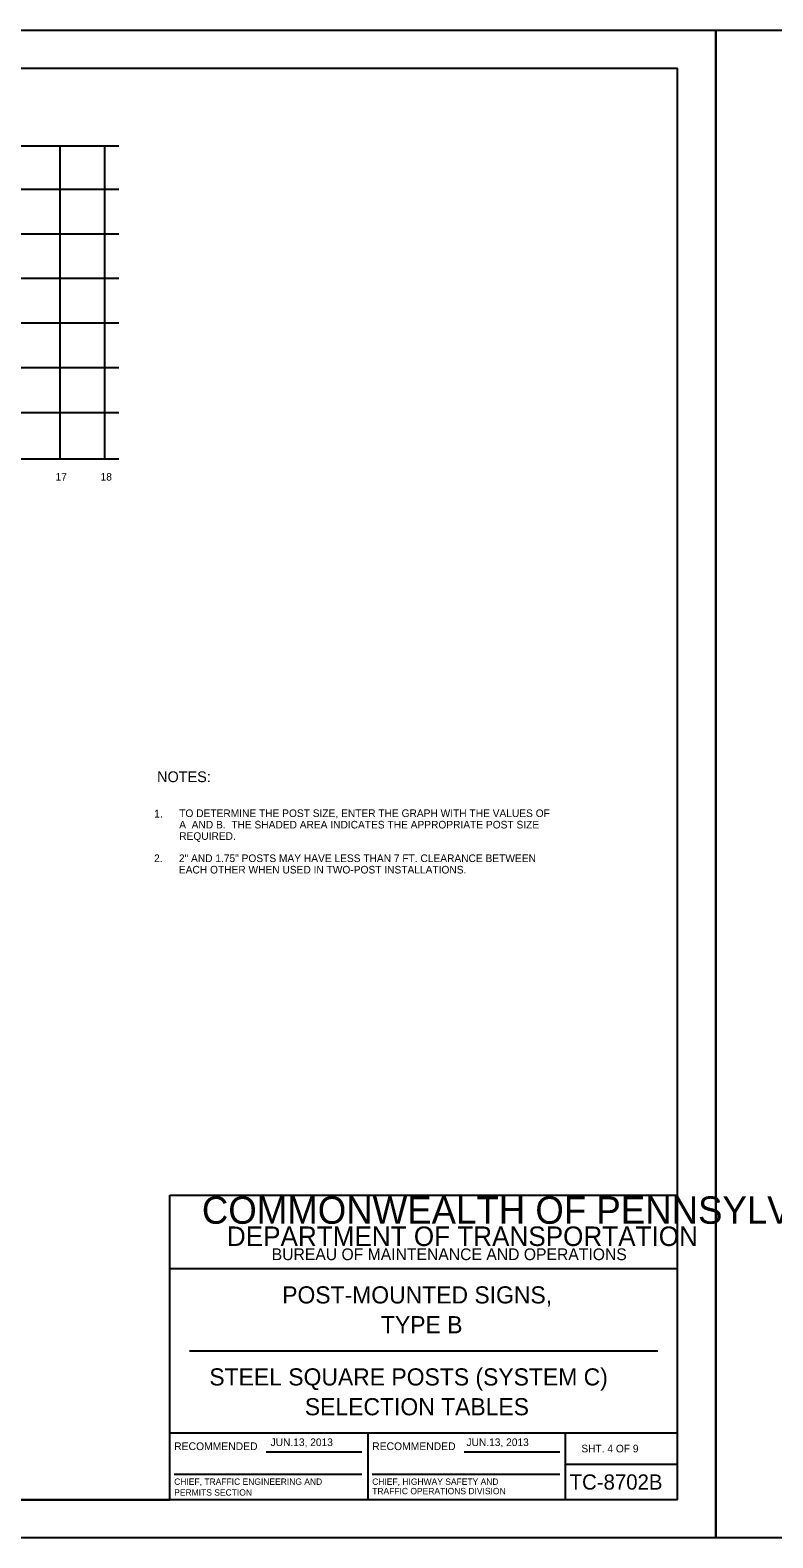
# Model space of a CAD drawing. Extents: x 644358 to 648627, y 294594 to 295782.
# Drawn here: x 647452 to 647745, y 295188 to 295782 of the extents above; entities that cross this region are included whole.
import ezdxf

# ---------------------------------------------------------------- set-up
doc = ezdxf.new("R2010")
doc.units = 0
for name, color, linetype in [('1', 7, 'Continuous'), ('2', 7, 'Continuous'), ('4', 7, 'Continuous'), ('PLT-BNDY', 7, 'Continuous')]:
    doc.layers.add(name, color=color, linetype=linetype)

msp = doc.modelspace()

# ---------------------------------------------------------------- linework, layer by layer
at = {"layer": '1'}
for p, q in [((646921.31, 295766.63), (647707.31, 295766.63)), ((647707.31, 295202.63), (647707.31, 295766.63)), ((647507.31, 295202.63), (647507.31, 295322.63)), ((647507.31, 295322.63), (647707.31, 295322.63)), ((647707.31, 295293.63), (647507.31, 295293.63)), ((647515.06, 295261.31), (647699.56, 295261.31)), ((647507.31, 295229), (647707.31, 295229)), ((647585.31, 295229), (647585.31, 295202.63)), ((647663.19, 295202.63), (647663.19, 295229)), ((647545.24, 295221.57), (647582.87, 295221.57)), ((647623.24, 295221.57), (647660.87, 295221.57)), ((647508.99, 295212.68), (647582.87, 295212.68)), ((647586.99, 295212.68), (647660.87, 295212.68)), ((647663.19, 295216.63), (647707.31, 295216.63)), ((647707.31, 295202.63), (646921.31, 295202.63)), ((646921.31, 295202.63), (647507.31, 295202.63))]:
    msp.add_line(p, q, dxfattribs=at)
at = {"layer": '2'}
for p, q in [((647487.16, 295735.97), (647252.91, 295735.97)), ((647464.03, 295612.54), (647464.03, 295735.97)), ((647481.66, 295612.54), (647481.66, 295735.97)), ((647487.16, 295718.91), (647252.91, 295718.91)), ((647487.16, 295701.29), (647252.91, 295701.29)), ((647487.16, 295683.79), (647252.91, 295683.79)), ((647487.16, 295666.16), (647252.91, 295666.16)), ((647252.91, 295648.66), (647487.16, 295648.66)), ((647306.03, 295631.04), (647487.16, 295631.04)), ((647487.16, 295612.54), (647252.91, 295612.54))]:
    msp.add_line(p, q, dxfattribs=at)
at = {"layer": 'PLT-BNDY'}
for points in [[(646881.31, 295781.63), (647722.31, 295781.63), (647722.31, 295187.63), (646881.31, 295187.63)], [(647722.31, 295781.63), (648563.31, 295781.63), (648563.31, 295187.63), (647722.31, 295187.63)]]:
    msp.add_lwpolyline(points, close=True, dxfattribs=at)

# ---------------------------------------------------------------- texts
at = {"layer": '1'}
for s, height, p in [('1. ', 3.089, (647501.08, 295471.38)), ('2. ', 3, (647501.07, 295453.86)), ('COMMONWEALTH OF PENNSYLVANIA', 10.7828, (647519.9, 295311.36)), ('DEPARTMENT OF TRANSPORTATION', 7.6837, (647529.76, 295302.61)), ('BUREAU OF MAINTENANCE AND OPERATIONS', 4.6253, (647547.41, 295297.04)), ('POST-MOUNTED SIGNS,', 6.75, (647551.54, 295279.97)), ('TYPE B', 6.75, (647590.45, 295268.22)), ('STEEL SQUARE POSTS (SYSTEM C)', 6.75, (647522.84, 295247.66)), ('SELECTION TABLES', 6.75, (647560.47, 295235.91)), ('RECOMMENDED', 3.048, (647508.99, 295222.2)), ('RECOMMENDED', 3.048, (647586.99, 295222.2)), ('SHT. 4 OF 9', 3, (647669.39, 295221.31)), ('TC-8702B', 6, (647664.77, 295206.63)), ('CHIEF, TRAFFIC ENGINEERING AND', 2.5, (647508.99, 295208.51)), ('PERMITS SECTION', 2.5, (647508.99, 295204.26)), ('TRAFFIC OPERATIONS DIVISION', 2.5, (647586.99, 295204.81)), ('CHIEF, HIGHWAY SAFETY AND', 2.5, (647586.99, 295208.51))]:
    msp.add_text(s, height=height, dxfattribs=at).set_placement(p)
at = {"layer": '2'}
for s, p in [('TO DETERMINE THE POST SIZE, ENTER THE GRAPH WITH THE VALUES OF ', (647510.98, 295471.61)), ('A  AND B.  THE SHADED AREA INDICATES THE APPROPRIATE POST SIZE ', (647510.98, 295467.11)), ('REQUIRED.', (647510.98, 295462.61)), ('2" AND 1.75" POSTS MAY HAVE LESS THAN 7 FT. CLEARANCE BETWEEN', (647510.86, 295453.87)), ('EACH OTHER WHEN USED IN TWO-POST INSTALLATIONS.', (647510.86, 295449.37)), ('JUN.13, 2013', (647546.98, 295223.79)), ('JUN.13, 2013', (647624.14, 295223.79))]:
    msp.add_text(s, height=3, dxfattribs=at).set_placement(p)
at = {"layer": '4'}
for s, height, p in [('17', 3, (647462.28, 295604.17)), ('18', 3, (647480, 295604.17)), ('NOTES:', 4.25, (647502.27, 295485.36))]:
    msp.add_text(s, height=height, dxfattribs=at).set_placement(p)

doc.saveas('drawing.dxf')
